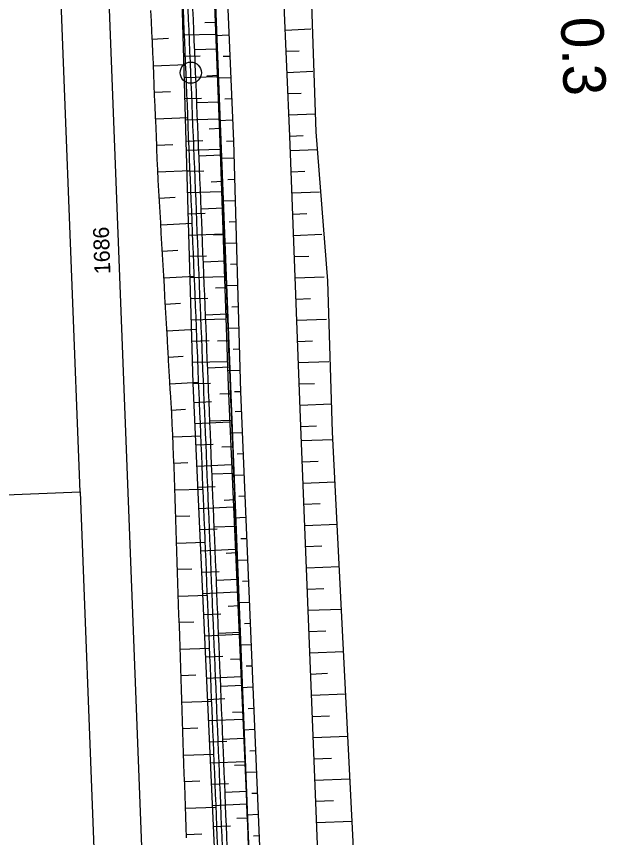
# Model space of a CAD drawing. Extents: x -583721 to -583071, y -1166145 to -1165065.
# Drawn here: x -583238.7 to -583183.1, y -1165900.9 to -1165823.5 of the extents above; entities that cross this region are included whole.
import ezdxf

# ---------------------------------------------------------------- set-up
doc = ezdxf.new("R2010")
doc.units = 0
for name, color, linetype in [('01_DOPRAVA', 7, 'Continuous'), ('14', 7, 'Continuous'), ('21', 7, 'Continuous'), ('_Rozpiska', 7, 'Continuous'), ('KOTY', 7, 'Continuous'), ('Parcelní čísla', 7, 'Continuous'), ('Popis cest', 7, 'Continuous'), ('Popis PP', 7, 'Continuous'), ('Rámy', 7, 'Continuous'), ('Trojúhelniky', 7, 'Continuous')]:
    doc.layers.add(name, color=color, linetype=linetype)

msp = doc.modelspace()

# ---------------------------------------------------------------- linework, layer by layer
at = {"layer": '01_DOPRAVA'}
for p, q in [((-583389.34, -1165874.81), (-583232.68, -1165868.31)), ((-583232.68, -1165868.31), (-583231.39, -1165901.9))]:
    msp.add_line(p, q, dxfattribs=at)
for points in [[(-583228.69, -1165666.2), (-583226.21, -1165672.99), (-583225.84, -1165679.92), (-583220.97, -1165796.08), (-583216.51, -1165909.44), (-583213.19, -1165995.13), (-583203.41, -1165993.97)], [(-583206.76, -1165905.62), (-583208.9, -1165862.71), (-583209.34, -1165848.45), (-583210.45, -1165834.4), (-583212.79, -1165765.14), (-583213.22, -1165730.9), (-583214.03, -1165712.42)], [(-583230.99, -1165795.18), (-583226.89, -1165901.72), (-583222.76, -1166003.69), (-583215.5, -1166006.52)], [(-583232.68, -1165868.31), (-583234.23, -1165827.88), (-583235.49, -1165795.36)]]:
    msp.add_lwpolyline(points, dxfattribs=at)
at = {"layer": '14'}
for p, q in [((-583220.93, -1165824.126), (-583219.868, -1165824.082)), ((-583224.357, -1165825.631), (-583225.879, -1165825.699)), ((-583221.889, -1165826.667), (-583219.77, -1165826.581)), ((-583225.767, -1165828.197), (-583222.732, -1165828.069)), ((-583220.729, -1165829.122), (-583219.672, -1165829.079)), ((-583224.149, -1165830.63), (-583225.669, -1165830.695)), ((-583221.685, -1165831.663), (-583219.573, -1165831.577)), ((-583225.555, -1165833.192), (-583222.528, -1165833.064)), ((-583220.529, -1165834.118), (-583219.475, -1165834.075)), ((-583223.941, -1165835.628), (-583225.457, -1165835.69)), ((-583221.48, -1165836.659), (-583219.377, -1165836.573)), ((-583225.349, -1165838.188), (-583222.324, -1165838.041)), ((-583220.328, -1165839.114), (-583219.279, -1165839.071)), ((-583223.719, -1165840.601), (-583225.216, -1165840.684)), ((-583221.276, -1165841.655), (-583219.18, -1165841.569)), ((-583225.072, -1165843.18), (-583222.121, -1165843.011)), ((-583220.128, -1165844.11), (-583219.082, -1165844.067)), ((-583223.474, -1165845.593), (-583224.929, -1165845.676)), ((-583221.071, -1165846.651), (-583218.984, -1165846.565)), ((-583224.786, -1165848.172), (-583221.916, -1165848.007)), ((-583219.927, -1165849.106), (-583218.885, -1165849.063)), ((-583223.229, -1165850.587), (-583224.643, -1165850.668)), ((-583220.866, -1165851.646), (-583218.787, -1165851.561)), ((-583224.5, -1165853.164), (-583221.712, -1165853.004)), ((-583219.727, -1165854.102), (-583218.689, -1165854.059)), ((-583222.983, -1165855.581), (-583224.357, -1165855.66)), ((-583220.662, -1165856.642), (-583218.591, -1165856.557)), ((-583224.214, -1165858.156), (-583221.507, -1165857.998)), ((-583219.526, -1165859.098), (-583218.492, -1165859.055)), ((-583222.736, -1165860.577), (-583224.068, -1165860.651)), ((-583220.457, -1165861.638), (-583218.394, -1165861.554)), ((-583223.936, -1165863.148), (-583221.301, -1165863.029)), ((-583219.325, -1165864.094), (-583218.296, -1165864.052)), ((-583222.52, -1165865.599), (-583223.842, -1165865.646)), ((-583220.253, -1165866.634), (-583218.197, -1165866.55)), ((-583223.758, -1165868.145), (-583221.095, -1165868.055)), ((-583219.125, -1165869.09), (-583218.099, -1165869.048)), ((-583222.334, -1165870.598), (-583223.674, -1165870.643)), ((-583220.048, -1165871.63), (-583218.001, -1165871.546)), ((-583223.591, -1165873.142), (-583220.891, -1165873.051)), ((-583218.924, -1165874.086), (-583217.903, -1165874.044)), ((-583222.148, -1165875.595), (-583223.507, -1165875.64)), ((-583219.844, -1165876.625), (-583217.804, -1165876.542)), ((-583223.423, -1165878.139), (-583220.686, -1165878.047)), ((-583218.724, -1165879.082), (-583217.706, -1165879.04)), ((-583221.962, -1165880.591), (-583223.34, -1165880.638)), ((-583219.639, -1165881.621), (-583217.608, -1165881.538)), ((-583223.256, -1165883.136), (-583220.482, -1165883.043)), ((-583218.523, -1165884.078), (-583217.509, -1165884.036)), ((-583221.776, -1165885.588), (-583223.173, -1165885.635)), ((-583219.435, -1165886.617), (-583217.411, -1165886.534)), ((-583223.089, -1165888.133), (-583220.277, -1165888.039)), ((-583218.323, -1165889.074), (-583217.313, -1165889.032)), ((-583221.59, -1165890.585), (-583223.005, -1165890.632)), ((-583219.23, -1165891.613), (-583217.215, -1165891.53)), ((-583222.922, -1165893.131), (-583220.073, -1165893.035)), ((-583218.122, -1165894.07), (-583217.116, -1165894.028)), ((-583221.404, -1165895.581), (-583222.838, -1165895.629)), ((-583219.026, -1165896.609), (-583217.018, -1165896.527)), ((-583222.754, -1165898.128), (-583219.869, -1165898.027)), ((-583217.922, -1165899.066), (-583216.92, -1165899.025)), ((-583221.215, -1165900.566), (-583222.663, -1165900.626))]:
    msp.add_line(p, q, dxfattribs=at)
at = {"layer": '21'}
for points in [[(-583222.65, -1165900.917), (-583222.695, -1165899.918), (-583222.728, -1165898.919), (-583222.761, -1165897.919), (-583222.795, -1165896.92), (-583222.828, -1165895.92), (-583222.862, -1165894.921), (-583222.895, -1165893.921), (-583222.929, -1165892.922), (-583222.962, -1165891.922), (-583222.996, -1165890.923), (-583223.029, -1165889.923), (-583223.062, -1165888.924), (-583223.096, -1165887.924), (-583223.129, -1165886.925), (-583223.163, -1165885.925), (-583223.196, -1165884.926), (-583223.23, -1165883.926), (-583223.263, -1165882.927), (-583223.297, -1165881.928), (-583223.33, -1165880.928), (-583223.364, -1165879.929), (-583223.397, -1165878.929), (-583223.43, -1165877.93), (-583223.464, -1165876.93), (-583223.497, -1165875.931), (-583223.531, -1165874.931), (-583223.564, -1165873.932), (-583223.598, -1165872.932), (-583223.631, -1165871.933), (-583223.665, -1165870.933), (-583223.698, -1165869.934), (-583223.731, -1165868.934), (-583223.765, -1165867.935), (-583223.798, -1165866.936), (-583223.832, -1165865.936), (-583223.865, -1165864.937), (-583223.899, -1165863.937), (-583223.946, -1165862.938), (-583223.996, -1165861.939), (-583224.05, -1165860.941), (-583224.11, -1165859.942), (-583224.169, -1165858.944), (-583224.183, -1165858.702), (-583224.226, -1165857.946), (-583224.283, -1165856.947), (-583224.341, -1165855.949), (-583224.394, -1165855.013), (-583224.398, -1165854.95), (-583224.455, -1165853.952), (-583224.512, -1165852.953), (-583224.57, -1165851.955), (-583224.627, -1165850.956), (-583224.684, -1165849.958), (-583224.741, -1165848.959), (-583224.798, -1165847.961), (-583224.856, -1165846.962), (-583224.913, -1165845.964), (-583224.97, -1165844.965), (-583225.027, -1165843.967), (-583225.085, -1165842.968), (-583225.142, -1165841.97), (-583225.199, -1165840.971), (-583225.256, -1165839.973), (-583225.313, -1165838.974), (-583225.358, -1165837.975), (-583225.404, -1165836.976), (-583225.446, -1165835.977), (-583225.46, -1165835.63), (-583225.485, -1165834.978), (-583225.525, -1165833.979), (-583225.564, -1165832.979), (-583225.609, -1165831.98), (-583225.655, -1165830.981), (-583225.701, -1165829.982), (-583225.741, -1165828.983), (-583225.769, -1165828.134), (-583225.776, -1165827.984), (-583225.821, -1165826.985), (-583225.866, -1165825.986), (-583225.911, -1165824.987), (-583225.956, -1165823.988), (-583226.001, -1165822.989)], [(-583219.714, -1165901.798), (-583219.755, -1165900.798), (-583219.796, -1165899.799), (-583219.837, -1165898.8), (-583219.878, -1165897.801), (-583219.919, -1165896.802), (-583219.96, -1165895.803), (-583220, -1165894.803), (-583220.041, -1165893.804), (-583220.082, -1165892.805), (-583220.123, -1165891.806), (-583220.164, -1165890.807), (-583220.205, -1165889.808), (-583220.246, -1165888.809), (-583220.287, -1165887.809), (-583220.328, -1165886.81), (-583220.369, -1165885.811), (-583220.41, -1165884.812), (-583220.45, -1165883.813), (-583220.491, -1165882.814), (-583220.532, -1165881.814), (-583220.573, -1165880.815), (-583220.614, -1165879.816), (-583220.655, -1165878.817), (-583220.696, -1165877.818), (-583220.737, -1165876.819), (-583220.778, -1165875.819), (-583220.819, -1165874.82), (-583220.859, -1165873.821), (-583220.9, -1165872.822), (-583220.941, -1165871.823), (-583220.982, -1165870.824), (-583221.023, -1165869.824), (-583221.064, -1165868.825), (-583221.105, -1165867.826), (-583221.146, -1165866.827), (-583221.187, -1165865.828), (-583221.228, -1165864.829), (-583221.268, -1165863.829), (-583221.309, -1165862.83), (-583221.35, -1165861.831), (-583221.391, -1165860.832), (-583221.432, -1165859.833), (-583221.473, -1165858.834), (-583221.483, -1165858.591), (-583221.514, -1165857.834), (-583221.555, -1165856.835), (-583221.596, -1165855.836), (-583221.634, -1165854.9), (-583221.637, -1165854.837), (-583221.678, -1165853.838), (-583221.718, -1165852.839), (-583221.759, -1165851.839), (-583221.8, -1165850.84), (-583221.841, -1165849.841), (-583221.882, -1165848.842), (-583221.923, -1165847.843), (-583221.964, -1165846.844), (-583222.005, -1165845.845), (-583222.046, -1165844.845), (-583222.087, -1165843.846), (-583222.127, -1165842.847), (-583222.168, -1165841.848), (-583222.209, -1165840.849), (-583222.25, -1165839.85), (-583222.291, -1165838.85), (-583222.332, -1165837.851), (-583222.373, -1165836.852), (-583222.414, -1165835.853), (-583222.428, -1165835.506), (-583222.455, -1165834.854), (-583222.496, -1165833.855), (-583222.537, -1165832.855), (-583222.577, -1165831.856), (-583222.618, -1165830.857), (-583222.659, -1165829.858), (-583222.7, -1165828.859), (-583222.735, -1165828.01), (-583222.741, -1165827.86), (-583222.782, -1165826.86), (-583222.823, -1165825.861), (-583222.864, -1165824.862), (-583222.905, -1165823.863), (-583222.946, -1165822.864)], [(-583218.815, -1165901.761), (-583218.856, -1165900.762), (-583218.897, -1165899.762), (-583218.938, -1165898.763), (-583218.979, -1165897.764), (-583219.019, -1165896.765), (-583219.06, -1165895.766), (-583219.101, -1165894.767), (-583219.142, -1165893.768), (-583219.183, -1165892.768), (-583219.224, -1165891.769), (-583219.265, -1165890.77), (-583219.306, -1165889.771), (-583219.347, -1165888.772), (-583219.388, -1165887.773), (-583219.428, -1165886.773), (-583219.469, -1165885.774), (-583219.51, -1165884.775), (-583219.551, -1165883.776), (-583219.592, -1165882.777), (-583219.633, -1165881.778), (-583219.674, -1165880.778), (-583219.715, -1165879.779), (-583219.756, -1165878.78), (-583219.797, -1165877.781), (-583219.837, -1165876.782), (-583219.878, -1165875.783), (-583219.919, -1165874.783), (-583219.96, -1165873.784), (-583220.001, -1165872.785), (-583220.042, -1165871.786), (-583220.083, -1165870.787), (-583220.124, -1165869.788), (-583220.165, -1165868.788), (-583220.206, -1165867.789), (-583220.247, -1165866.79), (-583220.287, -1165865.791), (-583220.328, -1165864.792), (-583220.369, -1165863.793), (-583220.41, -1165862.793), (-583220.451, -1165861.794), (-583220.492, -1165860.795), (-583220.533, -1165859.796), (-583220.574, -1165858.797), (-583220.584, -1165858.555), (-583220.615, -1165857.798), (-583220.656, -1165856.798), (-583220.696, -1165855.799), (-583220.735, -1165854.863), (-583220.737, -1165854.8), (-583220.778, -1165853.801), (-583220.819, -1165852.802), (-583220.86, -1165851.803), (-583220.901, -1165850.804), (-583220.942, -1165849.804), (-583220.983, -1165848.805), (-583221.024, -1165847.806), (-583221.065, -1165846.807), (-583221.106, -1165845.808), (-583221.146, -1165844.809), (-583221.187, -1165843.809), (-583221.228, -1165842.81), (-583221.269, -1165841.811), (-583221.31, -1165840.812), (-583221.351, -1165839.813), (-583221.392, -1165838.814), (-583221.433, -1165837.814), (-583221.474, -1165836.815), (-583221.515, -1165835.816), (-583221.529, -1165835.469), (-583221.555, -1165834.817), (-583221.596, -1165833.818), (-583221.637, -1165832.819), (-583221.678, -1165831.819), (-583221.719, -1165830.82), (-583221.76, -1165829.821), (-583221.801, -1165828.822), (-583221.836, -1165827.973), (-583221.842, -1165827.823), (-583221.883, -1165826.824), (-583221.924, -1165825.824), (-583221.965, -1165824.825), (-583222.005, -1165823.826), (-583222.046, -1165822.827)], [(-583216.815, -1165901.679), (-583216.855, -1165900.68), (-583216.894, -1165899.681), (-583216.933, -1165898.681), (-583216.973, -1165897.682), (-583217.012, -1165896.683), (-583217.051, -1165895.684), (-583217.091, -1165894.684), (-583217.13, -1165893.685), (-583217.169, -1165892.686), (-583217.208, -1165891.687), (-583217.248, -1165890.687), (-583217.287, -1165889.688), (-583217.326, -1165888.689), (-583217.366, -1165887.69), (-583217.405, -1165886.691), (-583217.444, -1165885.691), (-583217.484, -1165884.692), (-583217.523, -1165883.693), (-583217.562, -1165882.694), (-583217.602, -1165881.694), (-583217.641, -1165880.695), (-583217.68, -1165879.696), (-583217.72, -1165878.697), (-583217.759, -1165877.697), (-583217.798, -1165876.698), (-583217.837, -1165875.699), (-583217.877, -1165874.7), (-583217.916, -1165873.701), (-583217.955, -1165872.701), (-583217.995, -1165871.702), (-583218.034, -1165870.703), (-583218.073, -1165869.704), (-583218.113, -1165868.704), (-583218.152, -1165867.705), (-583218.191, -1165866.706), (-583218.231, -1165865.707), (-583218.27, -1165864.708), (-583218.309, -1165863.708), (-583218.349, -1165862.709), (-583218.388, -1165861.71), (-583218.427, -1165860.711), (-583218.467, -1165859.711), (-583218.506, -1165858.712), (-583218.515, -1165858.47), (-583218.545, -1165857.713), (-583218.584, -1165856.714), (-583218.624, -1165855.714), (-583218.661, -1165854.778), (-583218.663, -1165854.715), (-583218.702, -1165853.716), (-583218.742, -1165852.717), (-583218.781, -1165851.718), (-583218.82, -1165850.718), (-583218.86, -1165849.719), (-583218.899, -1165848.72), (-583218.938, -1165847.721), (-583218.978, -1165846.721), (-583219.017, -1165845.722), (-583219.056, -1165844.723), (-583219.096, -1165843.724), (-583219.135, -1165842.725), (-583219.174, -1165841.725), (-583219.213, -1165840.726), (-583219.253, -1165839.727), (-583219.292, -1165838.728), (-583219.331, -1165837.728), (-583219.371, -1165836.729), (-583219.41, -1165835.73), (-583219.424, -1165835.383), (-583219.449, -1165834.731), (-583219.489, -1165833.731), (-583219.528, -1165832.732), (-583219.567, -1165831.733), (-583219.607, -1165830.734), (-583219.646, -1165829.735), (-583219.685, -1165828.735), (-583219.719, -1165827.886), (-583219.725, -1165827.736), (-583219.764, -1165826.737), (-583219.803, -1165825.738), (-583219.842, -1165824.738), (-583219.882, -1165823.739), (-583219.921, -1165822.74)]]:
    msp.add_lwpolyline(points, dxfattribs=at)
at = {"layer": '_Rozpiska'}
for points in [[(-583222.97, -1165825.28), (-583219.92, -1165825.2)], [(-583218.66, -1165825.31), (-583219.92, -1165825.36)], [(-583213.35, -1165824.82), (-583210.96, -1165824.72)], [(-583213.26, -1165826.82), (-583212.06, -1165826.77)], [(-583222.91, -1165827.28), (-583221.38, -1165827.24)], [(-583218.57, -1165827.31), (-583219.21, -1165827.33)], [(-583222.85, -1165829.28), (-583219.77, -1165829.19)], [(-583213.18, -1165828.82), (-583210.75, -1165828.71)], [(-583218.49, -1165829.31), (-583219.76, -1165829.36)], [(-583213.09, -1165830.81), (-583211.87, -1165830.76)], [(-583222.8, -1165831.28), (-583221.24, -1165831.24)], [(-583218.4, -1165831.3), (-583219.04, -1165831.33)], [(-583213.01, -1165832.81), (-583210.54, -1165832.71)], [(-583222.74, -1165833.28), (-583219.61, -1165833.19)], [(-583218.32, -1165833.3), (-583219.61, -1165833.36)], [(-583222.68, -1165835.28), (-583221.11, -1165835.23)], [(-583218.23, -1165835.3), (-583218.88, -1165835.33)], [(-583212.92, -1165834.81), (-583211.68, -1165834.76)], [(-583222.66, -1165836.13), (-583219.51, -1165836.04)], [(-583212.87, -1165836.17), (-583210.36, -1165836.07)], [(-583218.19, -1165836.9), (-583219.48, -1165836.93)], [(-583222.6, -1165838.13), (-583221.02, -1165838.08)], [(-583212.79, -1165838.17), (-583211.52, -1165838.12)], [(-583218.13, -1165838.9), (-583218.77, -1165838.92)], [(-583222.54, -1165840.13), (-583219.37, -1165840.04)], [(-583212.72, -1165840.17), (-583210.14, -1165840.07)], [(-583218.07, -1165840.9), (-583219.34, -1165840.93)], [(-583222.48, -1165842.13), (-583220.89, -1165842.08)], [(-583212.64, -1165842.16), (-583211.34, -1165842.11)], [(-583218.02, -1165842.9), (-583218.64, -1165842.91)], [(-583222.42, -1165844.13), (-583219.23, -1165844.03)], [(-583212.57, -1165844.16), (-583209.92, -1165844.06)], [(-583217.96, -1165844.9), (-583219.2, -1165844.93)], [(-583222.37, -1165846.13), (-583220.77, -1165846.08)], [(-583212.49, -1165846.16), (-583211.15, -1165846.11)], [(-583217.91, -1165846.89), (-583218.52, -1165846.91)], [(-583222.31, -1165848.12), (-583219.1, -1165848.03)], [(-583212.42, -1165848.16), (-583209.7, -1165848.06)], [(-583217.85, -1165848.89), (-583219.06, -1165848.93)], [(-583222.25, -1165850.12), (-583220.64, -1165850.08)], [(-583212.34, -1165850.16), (-583210.97, -1165850.11)], [(-583217.79, -1165850.89), (-583218.39, -1165850.91)], [(-583222.19, -1165852.12), (-583218.96, -1165852.03)], [(-583212.27, -1165852.16), (-583209.48, -1165852.05)], [(-583217.74, -1165852.89), (-583218.93, -1165852.93)], [(-583222.14, -1165854.12), (-583220.51, -1165854.07)], [(-583212.19, -1165854.16), (-583210.78, -1165854.1)], [(-583217.68, -1165854.89), (-583218.27, -1165854.91)], [(-583222.08, -1165856.12), (-583218.82, -1165856.03)], [(-583212.12, -1165856.15), (-583209.26, -1165856.05)], [(-583217.63, -1165856.89), (-583218.79, -1165856.92)], [(-583222.02, -1165858.12), (-583220.39, -1165858.07)], [(-583212.04, -1165858.15), (-583210.6, -1165858.1)], [(-583217.57, -1165858.89), (-583218.15, -1165858.91)], [(-583221.94, -1165859.9), (-583220.31, -1165859.82)], [(-583211.97, -1165860.15), (-583209.05, -1165860.04)], [(-583217.49, -1165860.75), (-583218.06, -1165860.77)], [(-583221.85, -1165861.89), (-583218.59, -1165861.74)], [(-583211.89, -1165862.15), (-583210.41, -1165862.09)], [(-583217.41, -1165862.75), (-583218.54, -1165862.79)], [(-583221.76, -1165863.89), (-583220.13, -1165863.82)], [(-583211.84, -1165863.49), (-583208.87, -1165863.38)], [(-583217.32, -1165864.75), (-583217.89, -1165864.77)], [(-583211.76, -1165865.49), (-583210.26, -1165865.43)], [(-583221.66, -1165865.89), (-583218.41, -1165865.74)], [(-583217.24, -1165866.74), (-583218.37, -1165866.79)], [(-583221.57, -1165867.89), (-583219.95, -1165867.81)], [(-583211.68, -1165867.49), (-583208.67, -1165867.37)], [(-583217.16, -1165868.74), (-583217.72, -1165868.77)], [(-583211.6, -1165869.49), (-583210.08, -1165869.43)], [(-583221.48, -1165869.89), (-583218.24, -1165869.74)], [(-583217.07, -1165870.74), (-583218.19, -1165870.79)], [(-583211.52, -1165871.49), (-583208.47, -1165871.37)], [(-583221.39, -1165871.88), (-583219.77, -1165871.81)], [(-583216.99, -1165872.74), (-583217.54, -1165872.76)], [(-583221.3, -1165873.88), (-583218.06, -1165873.73)], [(-583211.44, -1165873.48), (-583209.91, -1165873.42)], [(-583216.91, -1165874.74), (-583218.01, -1165874.78)], [(-583211.36, -1165875.48), (-583208.27, -1165875.36)], [(-583221.21, -1165875.88), (-583219.59, -1165875.81)], [(-583216.82, -1165876.73), (-583217.37, -1165876.76)], [(-583221.12, -1165877.88), (-583217.88, -1165877.73)], [(-583211.28, -1165877.48), (-583209.73, -1165877.42)], [(-583216.74, -1165878.73), (-583217.83, -1165878.78)], [(-583211.21, -1165879.48), (-583208.07, -1165879.36)], [(-583221.03, -1165879.88), (-583219.41, -1165879.8)], [(-583216.65, -1165880.73), (-583217.2, -1165880.75)], [(-583220.93, -1165881.87), (-583217.7, -1165881.73)], [(-583211.13, -1165881.48), (-583209.55, -1165881.42)], [(-583216.57, -1165882.73), (-583217.66, -1165882.77)], [(-583211.05, -1165883.48), (-583207.87, -1165883.35)], [(-583220.84, -1165883.87), (-583219.23, -1165883.8)], [(-583216.49, -1165884.73), (-583217.03, -1165884.75)], [(-583210.97, -1165885.48), (-583209.37, -1165885.41)], [(-583220.75, -1165885.87), (-583217.53, -1165885.72)], [(-583216.4, -1165886.73), (-583217.48, -1165886.77)], [(-583220.66, -1165887.87), (-583219.05, -1165887.79)], [(-583210.89, -1165887.47), (-583207.67, -1165887.35)], [(-583216.32, -1165888.72), (-583216.85, -1165888.75)], [(-583210.81, -1165889.47), (-583209.19, -1165889.41)], [(-583220.57, -1165889.86), (-583217.35, -1165889.72)], [(-583216.24, -1165890.72), (-583217.3, -1165890.77)], [(-583220.48, -1165891.86), (-583218.87, -1165891.79)], [(-583210.73, -1165891.47), (-583207.47, -1165891.34)], [(-583216.15, -1165892.72), (-583216.68, -1165892.74)], [(-583210.65, -1165893.47), (-583209.01, -1165893.4)], [(-583220.39, -1165893.86), (-583217.17, -1165893.71)], [(-583216.07, -1165894.72), (-583217.12, -1165894.76)], [(-583210.57, -1165895.47), (-583207.27, -1165895.34)], [(-583220.3, -1165895.86), (-583218.69, -1165895.78)], [(-583215.98, -1165896.72), (-583216.51, -1165896.74)], [(-583220.2, -1165897.86), (-583216.99, -1165897.71)], [(-583210.5, -1165897.47), (-583208.83, -1165897.4)], [(-583215.9, -1165898.72), (-583216.95, -1165898.76)], [(-583210.42, -1165899.46), (-583207.07, -1165899.33)], [(-583220.11, -1165899.85), (-583218.51, -1165899.78)], [(-583215.82, -1165900.71), (-583216.34, -1165900.74)]]:
    msp.add_lwpolyline(points, dxfattribs=at)
at = {"layer": 'KOTY'}
msp.add_lwpolyline([(-583219.265, -1165901.779), (-583219.305, -1165900.78), (-583219.346, -1165899.781), (-583219.387, -1165898.782), (-583219.428, -1165897.783), (-583219.469, -1165896.783), (-583219.51, -1165895.784), (-583219.551, -1165894.785), (-583219.592, -1165893.786), (-583219.633, -1165892.787), (-583219.674, -1165891.788), (-583219.714, -1165890.788), (-583219.755, -1165889.789), (-583219.796, -1165888.79), (-583219.837, -1165887.791), (-583219.878, -1165886.792), (-583219.919, -1165885.793), (-583219.96, -1165884.793), (-583220.001, -1165883.794), (-583220.042, -1165882.795), (-583220.083, -1165881.796), (-583220.123, -1165880.797), (-583220.164, -1165879.798), (-583220.205, -1165878.798), (-583220.246, -1165877.799), (-583220.287, -1165876.8), (-583220.328, -1165875.801), (-583220.369, -1165874.802), (-583220.41, -1165873.803), (-583220.451, -1165872.804), (-583220.492, -1165871.804), (-583220.533, -1165870.805), (-583220.573, -1165869.806), (-583220.614, -1165868.807), (-583220.655, -1165867.808), (-583220.696, -1165866.809), (-583220.737, -1165865.809), (-583220.778, -1165864.81), (-583220.819, -1165863.811), (-583220.86, -1165862.812), (-583220.901, -1165861.813), (-583220.942, -1165860.814), (-583220.982, -1165859.814), (-583221.023, -1165858.815), (-583221.033, -1165858.573), (-583221.064, -1165857.816), (-583221.105, -1165856.817), (-583221.146, -1165855.818), (-583221.184, -1165854.882), (-583221.187, -1165854.819), (-583221.228, -1165853.819), (-583221.269, -1165852.82), (-583221.31, -1165851.821), (-583221.351, -1165850.822), (-583221.392, -1165849.823), (-583221.432, -1165848.824), (-583221.473, -1165847.824), (-583221.514, -1165846.825), (-583221.555, -1165845.826), (-583221.596, -1165844.827), (-583221.637, -1165843.828), (-583221.678, -1165842.829), (-583221.719, -1165841.829), (-583221.76, -1165840.83), (-583221.801, -1165839.831), (-583221.841, -1165838.832), (-583221.882, -1165837.833), (-583221.923, -1165836.834), (-583221.964, -1165835.834), (-583221.978, -1165835.487), (-583222.005, -1165834.835), (-583222.046, -1165833.836), (-583222.087, -1165832.837), (-583222.128, -1165831.838), (-583222.169, -1165830.839), (-583222.21, -1165829.839), (-583222.251, -1165828.84), (-583222.285, -1165827.992), (-583222.291, -1165827.841), (-583222.332, -1165826.842), (-583222.373, -1165825.843), (-583222.414, -1165824.844), (-583222.455, -1165823.845), (-583222.496, -1165822.845)], dxfattribs=at)
at = {"layer": 'Popis cest'}
for points in [[(-583214.565, -1166024.741), (-583215.84, -1165999.86), (-583216.56, -1165980.47), (-583218.74, -1165935.28), (-583219.93, -1165903.85), (-583222.02, -1165858.12), (-583222.68, -1165835.28), (-583223.83, -1165795.43), (-583225.18, -1165766.01), (-583226.29, -1165730.41), (-583226.47, -1165703.12), (-583228.25, -1165673.5)], [(-583202.046, -1166023.279), (-583203.28, -1165999.31), (-583203.79, -1165978.24), (-583205.99, -1165934.1), (-583206.83, -1165909.26), (-583206.76, -1165905.62), (-583208.9, -1165862.71), (-583209.34, -1165848.45), (-583210.45, -1165834.4), (-583212.79, -1165765.14), (-583213.22, -1165730.9), (-583214.43, -1165703.46)]]:
    msp.add_lwpolyline(points, dxfattribs=at)
at = {"layer": 'Popis PP'}
for points in [[(-583205.384, -1166023.669), (-583206.37, -1165999.45), (-583206.99, -1165978.09), (-583208.8, -1165934.4), (-583209.98, -1165909.96), (-583210.18, -1165905.46), (-583211.89, -1165862.15), (-583212.92, -1165834.81), (-583214.61, -1165795.62), (-583215.68, -1165765.46), (-583217.22, -1165730.71), (-583218.84, -1165703.6), (-583219.86, -1165675.86), (-583220.15, -1165659.61)], [(-583225.03, -1165669.36), (-583224.72, -1165676.77), (-583223.57, -1165703.33), (-583222.76, -1165730.88), (-583221.39, -1165765.94), (-583219.92, -1165795.75), (-583218.23, -1165835.3), (-583217.57, -1165858.89), (-583215.65, -1165904.71), (-583214.33, -1165934.9), (-583212.44, -1165979.07), (-583211.41, -1165999.47), (-583210.642, -1166024.283)]]:
    msp.add_lwpolyline(points, dxfattribs=at)
at = {"layer": 'Rámy'}
msp.add_lwpolyline([(-583225.84, -1165679.92), (-583224.89, -1165703.34), (-583223.84, -1165730.71), (-583222.52, -1165765.99), (-583221.05, -1165795.86), (-583219.53, -1165835.39), (-583218.74, -1165858.37), (-583216.69, -1165904.53), (-583215.95, -1165934.96), (-583213.79, -1165980.28), (-583213.02, -1165999.42)], dxfattribs=at)
at = {"layer": 'Trojúhelniky'}
msp.add_circle((-583222.251, -1165828.84), 1, dxfattribs=at)
msp.add_circle((-583222.251, -1165828.84), 1, dxfattribs=at)

# ---------------------------------------------------------------- texts
at = {"layer": 'Parcelní čísla'}
msp.add_text('1686', height=1.5, rotation=92, dxfattribs=at).set_placement((-583229.815, -1165847.786))
at = {"layer": 'Trojúhelniky'}
msp.add_text('0.3', height=4, rotation=272.3443, dxfattribs=at).set_placement((-583187.433, -1165823.656))

doc.saveas('drawing.dxf')
